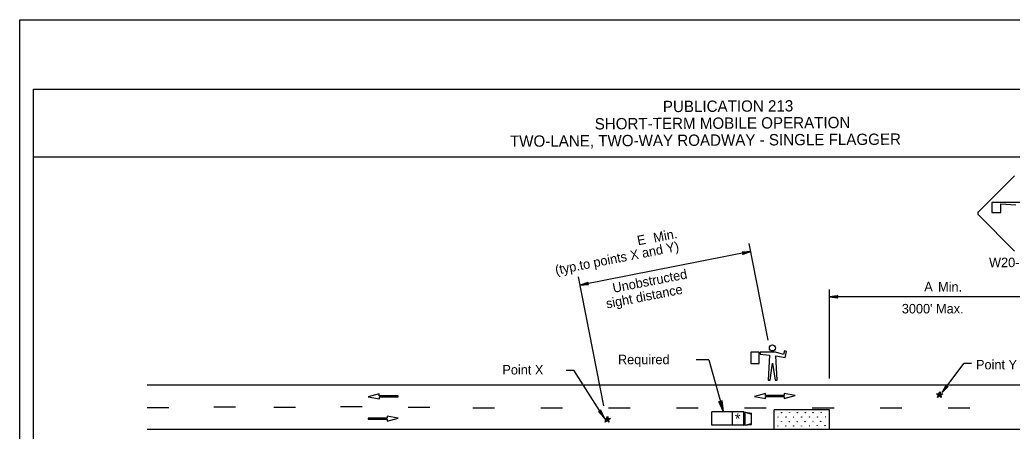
# Model space of a CAD drawing. Extents: x -14145 to -13521, y 30244 to 30661.
# Drawn here: x -13892.17 to -13870.25, y 30468.21 to 30477.31 of the extents above; entities that cross this region are included whole.
import ezdxf

# ---------------------------------------------------------------- set-up
doc = ezdxf.new("R2010")
doc.units = 0
for name, color, linetype in [('1', 7, 'Continuous'), ('10', 7, 'Continuous'), ('2', 7, 'Continuous'), ('4', 7, 'Continuous'), ('61', 7, 'Continuous')]:
    doc.layers.add(name, color=color, linetype=linetype)

msp = doc.modelspace()

# ---------------------------------------------------------------- linework, layer by layer
at = {"layer": '1'}
for p, q in [((-13870.202, 30473.858), (-13870.997, 30473.063)), ((-13870.082, 30473.266), (-13870.705, 30473.266)), ((-13870.705, 30473.266), (-13870.705, 30473.048)), ((-13870.502, 30473.048), (-13870.502, 30473.243)), ((-13870.502, 30473.243), (-13870.172, 30473.221)), ((-13870.997, 30472.996), (-13870.202, 30472.193)), ((-13870.705, 30473.048), (-13870.502, 30473.048)), ((-13875.646, 30470.225), (-13876.065, 30472.362)), ((-13876.03, 30472.183), (-13879.799, 30471.444)), ((-13879.275, 30468.771), (-13879.834, 30471.623)), ((-13874.291, 30469.377), (-13874.291, 30471.347)), ((-13869.407, 30471.182), (-13874.291, 30471.182)), ((-13875.84, 30469.961), (-13876.028, 30469.961)), ((-13876.028, 30469.961), (-13876.028, 30469.711)), ((-13875.84, 30469.711), (-13875.84, 30469.961)), ((-13875.482, 30469.961), (-13875.822, 30469.961)), ((-13875.822, 30469.961), (-13875.822, 30469.917)), ((-13875.822, 30469.917), (-13875.616, 30469.891)), ((-13875.616, 30469.891), (-13875.644, 30469.345)), ((-13875.304, 30469.909), (-13875.482, 30469.961)), ((-13875.447, 30469.345), (-13875.473, 30469.881)), ((-13875.473, 30469.881), (-13875.268, 30469.843)), ((-13875.286, 30469.989), (-13875.304, 30469.909)), ((-13875.238, 30469.977), (-13875.286, 30469.989)), ((-13875.268, 30469.843), (-13875.238, 30469.977)), ((-13876.956, 30469.791), (-13877.236, 30469.791)), ((-13876.956, 30469.791), (-13876.638, 30468.659)), ((-13876.028, 30469.711), (-13875.84, 30469.711)), ((-13875.599, 30469.345), (-13875.545, 30469.719)), ((-13875.545, 30469.719), (-13875.492, 30469.345)), ((-13871.803, 30469.07), (-13871.32, 30469.708)), ((-13871.156, 30469.708), (-13871.32, 30469.708)), ((-13880.103, 30469.565), (-13879.938, 30469.565)), ((-13879.268, 30468.509), (-13879.937, 30469.565)), ((-13889.363, 30469.241), (-13863.083, 30469.241)), ((-13875.644, 30469.345), (-13875.599, 30469.345)), ((-13875.492, 30469.345), (-13875.447, 30469.345)), ((-13884.234, 30469.039), (-13884.476, 30468.973)), ((-13884.476, 30468.973), (-13884.232, 30468.926)), ((-13884.234, 30468.994), (-13884.234, 30469.039)), ((-13883.818, 30468.994), (-13884.234, 30468.994)), ((-13884.232, 30468.926), (-13884.232, 30468.972)), ((-13884.232, 30468.972), (-13883.818, 30468.972)), ((-13883.818, 30468.972), (-13883.818, 30468.994)), ((-13875.706, 30469.048), (-13875.947, 30468.982)), ((-13875.947, 30468.982), (-13875.704, 30468.936)), ((-13875.706, 30469.003), (-13875.706, 30469.048)), ((-13875.292, 30469.003), (-13875.706, 30469.003)), ((-13875.704, 30468.981), (-13875.29, 30468.981)), ((-13875.704, 30468.936), (-13875.704, 30468.981)), ((-13875.048, 30469.002), (-13875.292, 30469.048)), ((-13875.292, 30469.048), (-13875.292, 30469.003)), ((-13875.29, 30468.936), (-13875.048, 30469.002)), ((-13875.29, 30468.981), (-13875.29, 30468.936)), ((-13871.888, 30469.012), (-13871.902, 30468.961)), ((-13888.883, 30468.731), (-13889.363, 30468.731)), ((-13887.407, 30468.743), (-13887.887, 30468.743)), ((-13886.087, 30468.737), (-13886.567, 30468.737)), ((-13884.611, 30468.749), (-13885.091, 30468.749)), ((-13883.117, 30468.737), (-13883.597, 30468.737)), ((-13881.689, 30468.725), (-13882.169, 30468.725)), ((-13880.189, 30468.725), (-13880.669, 30468.725)), ((-13878.689, 30468.725), (-13879.169, 30468.725)), ((-13877.189, 30468.725), (-13877.669, 30468.725)), ((-13875.689, 30468.725), (-13876.169, 30468.725)), ((-13874.189, 30468.725), (-13874.669, 30468.725)), ((-13872.689, 30468.725), (-13873.169, 30468.725)), ((-13871.189, 30468.725), (-13871.669, 30468.725)), ((-13884.062, 30468.503), (-13884.476, 30468.503)), ((-13884.476, 30468.503), (-13884.476, 30468.481)), ((-13883.818, 30468.502), (-13884.062, 30468.548)), ((-13884.062, 30468.548), (-13884.062, 30468.503)), ((-13876.891, 30468.347), (-13876.891, 30468.642)), ((-13876.178, 30468.642), (-13876.891, 30468.642)), ((-13876.43, 30468.347), (-13876.43, 30468.642)), ((-13876.178, 30468.347), (-13876.178, 30468.642)), ((-13876.178, 30468.642), (-13876.012, 30468.613)), ((-13876.149, 30468.635), (-13876.012, 30468.592)), ((-13876.149, 30468.347), (-13876.149, 30468.635)), ((-13876.012, 30468.361), (-13876.012, 30468.613)), ((-13874.291, 30468.683), (-13875.515, 30468.683)), ((-13875.515, 30468.257), (-13875.515, 30468.683)), ((-13874.291, 30468.257), (-13874.291, 30468.683)), ((-13884.476, 30468.481), (-13884.059, 30468.481)), ((-13884.059, 30468.436), (-13883.818, 30468.502)), ((-13884.059, 30468.481), (-13884.059, 30468.436)), ((-13879.23, 30468.465), (-13879.244, 30468.415)), ((-13876.178, 30468.347), (-13876.891, 30468.347)), ((-13876.178, 30468.347), (-13876.012, 30468.361)), ((-13876.149, 30468.347), (-13876.012, 30468.383)), ((-13889.363, 30468.257), (-13863.083, 30468.257))]:
    msp.add_line(p, q, dxfattribs=at)
for points in [[(-13876.21, 30472.17), (-13876.202, 30472.16), (-13876.029, 30472.183), (-13876.21, 30472.17), (-13876.217, 30472.175), (-13876.029, 30472.183), (-13876.198, 30472.142), (-13876.202, 30472.129), (-13876.029, 30472.183), (-13876.205, 30472.116), (-13876.202, 30472.129)], [(-13879.617, 30471.457), (-13879.625, 30471.467), (-13879.798, 30471.444), (-13879.617, 30471.457), (-13879.61, 30471.452), (-13879.798, 30471.444), (-13879.629, 30471.485), (-13879.625, 30471.498), (-13879.798, 30471.444), (-13879.622, 30471.511), (-13879.625, 30471.498)], [(-13874.111, 30471.164), (-13874.117, 30471.176), (-13874.291, 30471.182), (-13874.111, 30471.164), (-13874.105, 30471.152), (-13874.291, 30471.182), (-13874.123, 30471.194), (-13874.117, 30471.206), (-13874.291, 30471.182), (-13874.105, 30471.212), (-13874.117, 30471.206)], [(-13871.679, 30469.201), (-13871.692, 30469.197), (-13871.803, 30469.07), (-13871.679, 30469.201), (-13871.666, 30469.204), (-13871.803, 30469.07), (-13871.706, 30469.214), (-13871.717, 30469.222), (-13871.803, 30469.07), (-13871.713, 30469.233), (-13871.717, 30469.222)], [(-13876.67, 30468.876), (-13876.683, 30468.864), (-13876.638, 30468.659), (-13876.67, 30468.876), (-13876.664, 30468.89), (-13876.638, 30468.659), (-13876.704, 30468.858), (-13876.721, 30468.861), (-13876.638, 30468.659), (-13876.735, 30468.87), (-13876.721, 30468.861)], [(-13879.347, 30468.671), (-13879.348, 30468.658), (-13879.268, 30468.509), (-13879.347, 30468.671), (-13879.345, 30468.684), (-13879.268, 30468.509), (-13879.369, 30468.65), (-13879.38, 30468.643), (-13879.268, 30468.509), (-13879.389, 30468.651), (-13879.38, 30468.643)]]:
    msp.add_lwpolyline(points, dxfattribs=at)
for centre, radius in [((-13875.55, 30470.055), 0.0672), ((-13875.425, 30468.524), 0.00272), ((-13875.345, 30468.622), 0.00272), ((-13875.25, 30468.526), 0.00272), ((-13875.172, 30468.623), 0.00272), ((-13875.079, 30468.524), 0.00272), ((-13874.998, 30468.624), 0.00272), ((-13874.903, 30468.526), 0.00272), ((-13874.824, 30468.623), 0.00272), ((-13874.729, 30468.525), 0.00272), ((-13874.652, 30468.625), 0.00272), ((-13874.557, 30468.53), 0.00272), ((-13874.556, 30468.527), 0.00272), ((-13874.477, 30468.628), 0.00272), ((-13874.382, 30468.532), 0.00272), ((-13875.43, 30468.328), 0.00272), ((-13875.35, 30468.425), 0.00272), ((-13875.255, 30468.33), 0.00272), ((-13875.179, 30468.425), 0.00272), ((-13875.082, 30468.329), 0.00272), ((-13875.002, 30468.426), 0.00272), ((-13874.908, 30468.331), 0.00272), ((-13874.829, 30468.426), 0.00272), ((-13874.735, 30468.332), 0.00272), ((-13874.654, 30468.428), 0.00272), ((-13874.562, 30468.335), 0.00272), ((-13874.561, 30468.332), 0.00272), ((-13874.483, 30468.432), 0.00272), ((-13874.388, 30468.336), 0.00272)]:
    msp.add_circle(centre, radius, dxfattribs=at)
msp.add_arc((-13870.969, 30473.027), 0.0465, 135, 225, dxfattribs=at)
at = {"layer": '10'}
for p, q in [((-13891.874, 30475.777), (-13860.422, 30475.777)), ((-13891.874, 30453.207), (-13891.874, 30475.777)), ((-13891.874, 30474.277), (-13860.422, 30474.277))]:
    msp.add_line(p, q, dxfattribs=at)
at = {"layer": '2'}
for p, q in [((-13871.888, 30469.012), (-13871.924, 30469.041)), ((-13871.924, 30469.041), (-13871.873, 30469.041)), ((-13871.902, 30468.961), (-13871.888, 30469.012)), ((-13871.859, 30468.997), (-13871.902, 30468.961)), ((-13871.873, 30469.041), (-13871.852, 30469.091)), ((-13871.823, 30468.961), (-13871.859, 30468.997)), ((-13871.852, 30469.091), (-13871.837, 30469.041)), ((-13871.837, 30469.041), (-13871.787, 30469.041)), ((-13871.787, 30469.041), (-13871.83, 30469.012)), ((-13871.83, 30469.012), (-13871.823, 30468.961)), ((-13879.215, 30468.494), (-13879.194, 30468.544)), ((-13879.194, 30468.544), (-13879.179, 30468.494)), ((-13879.23, 30468.465), (-13879.266, 30468.494)), ((-13879.266, 30468.494), (-13879.215, 30468.494)), ((-13879.244, 30468.415), (-13879.23, 30468.465)), ((-13879.201, 30468.451), (-13879.244, 30468.415)), ((-13879.165, 30468.415), (-13879.201, 30468.451)), ((-13879.179, 30468.494), (-13879.129, 30468.494)), ((-13879.129, 30468.494), (-13879.172, 30468.465)), ((-13879.172, 30468.465), (-13879.165, 30468.415))]:
    msp.add_line(p, q, dxfattribs=at)
for points in [[(-13871.859, 30469.069), (-13871.866, 30469.033), (-13871.909, 30469.033), (-13871.881, 30469.019), (-13871.895, 30468.976), (-13871.859, 30468.997), (-13871.823, 30468.976), (-13871.837, 30469.019), (-13871.801, 30469.033), (-13871.845, 30469.033), (-13871.852, 30469.077), (-13871.859, 30469.026), (-13871.895, 30469.033), (-13871.873, 30469.019), (-13871.888, 30468.983), (-13871.859, 30469.005), (-13871.83, 30468.983), (-13871.845, 30469.019), (-13871.816, 30469.033), (-13871.845, 30469.033), (-13871.852, 30469.055), (-13871.859, 30469.026), (-13871.881, 30469.026), (-13871.866, 30469.019), (-13871.873, 30468.997), (-13871.859, 30469.012), (-13871.845, 30468.997), (-13871.845, 30469.019), (-13871.823, 30469.026), (-13871.845, 30469.026), (-13871.852, 30469.033), (-13871.852, 30469.019), (-13871.866, 30469.019), (-13871.866, 30469.019), (-13871.866, 30469.005), (-13871.859, 30469.012), (-13871.845, 30469.005), (-13871.852, 30469.019), (-13871.837, 30469.019), (-13871.852, 30469.019), (-13871.852, 30469.019), (-13871.859, 30469.019), (-13871.859, 30469.019), (-13871.852, 30469.012), (-13871.859, 30469.019), (-13871.859, 30469.019), (-13871.859, 30469.019), (-13871.859, 30469.019)], [(-13879.201, 30468.523), (-13879.208, 30468.487), (-13879.251, 30468.487), (-13879.223, 30468.472), (-13879.237, 30468.429), (-13879.201, 30468.451), (-13879.165, 30468.429), (-13879.179, 30468.472), (-13879.143, 30468.487), (-13879.187, 30468.487), (-13879.194, 30468.53), (-13879.201, 30468.48), (-13879.237, 30468.487), (-13879.215, 30468.472), (-13879.23, 30468.436), (-13879.201, 30468.458), (-13879.172, 30468.436), (-13879.187, 30468.472), (-13879.158, 30468.487), (-13879.187, 30468.487), (-13879.194, 30468.508), (-13879.201, 30468.48), (-13879.223, 30468.48), (-13879.208, 30468.472), (-13879.215, 30468.451), (-13879.201, 30468.465), (-13879.187, 30468.451), (-13879.187, 30468.472), (-13879.165, 30468.48), (-13879.187, 30468.48), (-13879.194, 30468.487), (-13879.194, 30468.472), (-13879.208, 30468.472), (-13879.208, 30468.472), (-13879.208, 30468.458), (-13879.201, 30468.465), (-13879.187, 30468.458), (-13879.194, 30468.472), (-13879.179, 30468.472), (-13879.194, 30468.472), (-13879.194, 30468.472), (-13879.201, 30468.472), (-13879.201, 30468.472), (-13879.194, 30468.465), (-13879.201, 30468.472), (-13879.201, 30468.472), (-13879.201, 30468.472), (-13879.201, 30468.472)]]:
    msp.add_lwpolyline(points, dxfattribs=at)
at = {"layer": '61'}
msp.add_lwpolyline([(-13892.174, 30477.307), (-13859.174, 30477.307), (-13859.174, 30451.807), (-13892.174, 30451.807)], close=True, dxfattribs=at)

# ---------------------------------------------------------------- texts
at = {"layer": '1'}
msp.add_text('*', height=0.238, rotation=0.7233, dxfattribs=at).set_placement((-13876.376, 30468.37))
at = {"layer": '2'}
for s, p in [('E', (-13878.516, 30472.321)), ('Min.', (-13878.159, 30472.384)), ('(typ.to points X and Y)', (-13880.327, 30471.67)), ('Unobstructed', (-13879.058, 30471.271)), ('sight distance', (-13879.205, 30470.925))]:
    msp.add_text(s, height=0.21, rotation=11.0819, dxfattribs=at).set_placement(p)
for s, p in [('W20-7A', (-13870.765, 30471.839)), ('A', (-13872.196, 30471.306)), ('Min.', (-13871.891, 30471.301)), ("3000' Max.", (-13872.692, 30470.817)), ('Required', (-13878.962, 30469.694)), ('Point X', (-13881.515, 30469.467)), ('Point Y', (-13871.053, 30469.58))]:
    msp.add_text(s, height=0.21, dxfattribs=at).set_placement(p)
at = {"layer": '4'}
for s, p in [('PUBLICATION 213', (-13877.969, 30475.266)), ('SHORT-TERM MOBILE OPERATION', (-13879.475, 30474.883)), ('TWO-LANE, TWO-WAY ROADWAY - SINGLE FLAGGER', (-13881.347, 30474.499))]:
    msp.add_text(s, height=0.25, rotation=0.31, dxfattribs=at).set_placement(p)

doc.saveas('drawing.dxf')
